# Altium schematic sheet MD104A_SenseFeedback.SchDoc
size Letter; Date: Not shown in title block; ApprovedBy: Not shown in title block; CheckedBy: Not shown in title block; Author: Not shown in title block; CompanyName: Not shown in title block; Engineer: Not shown in title block; Organization: Not shown in title block; Address1: Not shown in title block; Address2: Not shown in title block; Address3: Not shown in title block; Address4: Not shown in title block; DocumentNumber: 3; Revision: Use project parameter SCH_Rev; SheetNumber: 3; SheetTotal: 5; PageSetup: Record=PageOptions¦CenterHorizontal=True¦CenterVertical=True¦PrintScale=1.00¦XCorrection=1.00¦YCorrection=1.00¦PrintKind=0¦BorderSize=5000000¦LeftOffset=0¦BottomOffset=0¦Orientation=2¦PaperLength=1000¦PaperWidth=1000¦Scale=100¦PaperSource=15¦PrintQuality=600¦MediaType=1¦DitherType=10¦PaperKind=Letter¦PrintScaleMode=1
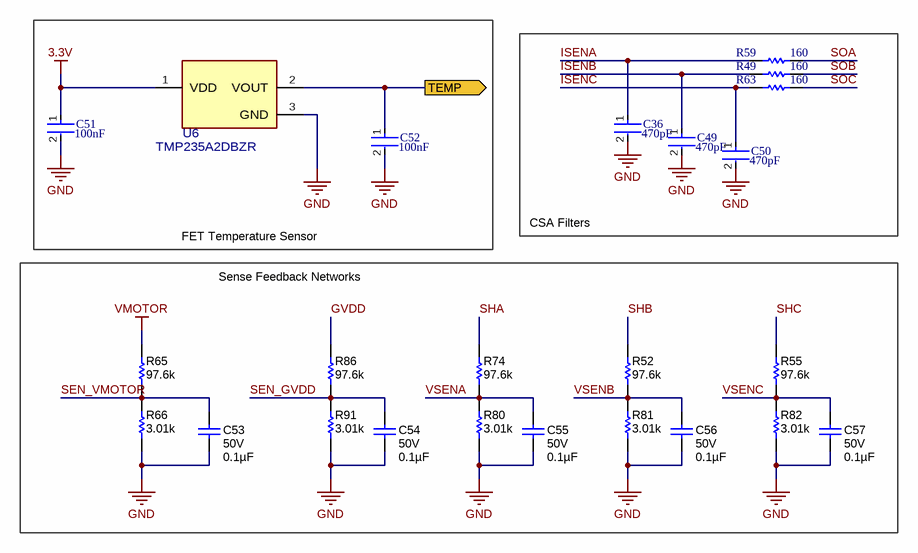
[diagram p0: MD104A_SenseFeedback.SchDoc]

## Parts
C36  Capacitance: 470pF  [FP-CL10-IPC_A]  (hidden comment: CL10C471JB81PNL)
C49  Capacitance: 470pF  [FP-CL10-IPC_A]  (hidden comment: CL10C471JB81PNL)
C50  Capacitance: 470pF  [FP-CL10-IPC_A]  (hidden comment: CL10C471JB81PNL)
C51  Capacitance: 100nF  [FP-GCM155-0_05-IPC_A]  (hidden comment: GCM155R71C104KA55J)
C52  Capacitance: 100nF  [FP-GCM155-0_05-IPC_A]  (hidden comment: GCM155R71C104KA55J)
C53  Value2: 50V  ValueDisplayed: 0.1µF  [0603L]  (hidden comment: C0603C104K5RACAUTO)
C54  Value2: 50V  ValueDisplayed: 0.1µF  [0603L]  (hidden comment: C0603C104K5RACAUTO)
C55  Value2: 50V  ValueDisplayed: 0.1µF  [0603L]  (hidden comment: C0603C104K5RACAUTO)
C56  Value2: 50V  ValueDisplayed: 0.1µF  [0603L]  (hidden comment: C0603C104K5RACAUTO)
C57  Value2: 50V  ValueDisplayed: 0.1µF  [0603L]  (hidden comment: C0603C104K5RACAUTO)
R49  160  [RESC1608X55X30ML15T15]
R52  ValueDisplayed: 97.6k  [0603L]  (hidden comment: CRCW060397K6FKEA)
R55  ValueDisplayed: 97.6k  [0603L]  (hidden comment: CRCW060397K6FKEA)
R59  160  [RESC1608X55X30ML15T15]
R63  160  [RESC1608X55X30ML15T15]
R65  ValueDisplayed: 97.6k  [0603L]  (hidden comment: CRCW060397K6FKEA)
R66  ValueDisplayed: 3.01k  [0603L]  (hidden comment: CRCW06033K01FKEA)
R74  ValueDisplayed: 97.6k  [0603L]  (hidden comment: CRCW060397K6FKEA)
R80  ValueDisplayed: 3.01k  [0603L]  (hidden comment: CRCW06033K01FKEA)
R81  ValueDisplayed: 3.01k  [0603L]  (hidden comment: CRCW06033K01FKEA)
R82  ValueDisplayed: 3.01k  [0603L]  (hidden comment: CRCW06033K01FKEA)
R86  ValueDisplayed: 97.6k  [0603L]  (hidden comment: CRCW060397K6FKEA)
R91  ValueDisplayed: 3.01k  [0603L]  (hidden comment: CRCW06033K01FKEA)
U6  TMP235A2DBZR  [DBZ0003A-MFG]

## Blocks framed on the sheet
FET Temperature Sensor: C51 C52 U6
CSA Filters: C36 C49 C50 R49 R59 R63
Sense Feedback Networks: C53-C57 R52 R55 R65 R66 R74 R80-R82 R86 R91

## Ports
TEMP (out)

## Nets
3.3V: C51.1 U6.1(VDD)
GND: C36.2 C49.2 C50.2 C51.2 C52.2 C53.1 C54.1 C55.1 C56.1 C57.1 R66.1 R80.1 R81.1 R82.1 R91.1 U6.3(GND)
VMOTOR: R65.2
GVDD: R86.2
ISENA: C36.1 R59.1
ISENB: C49.1 R49.1
ISENC: C50.1 R63.1
SEN_GVDD: C54.2 R86.1 R91.2
SEN_VMOTOR: C53.2 R65.1 R66.2
SHA: R74.2
SHB: R52.2
SHC: R55.2
SOA: R59.2
SOB: R49.2
SOC: R63.2
TEMP: C52.1 U6.2(VOUT) ; port TEMP
VSENA: C55.2 R74.1 R80.2
VSENB: C56.2 R52.1 R81.2
VSENC: C57.2 R55.1 R82.2

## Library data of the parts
C36 C49 C50 = CMP-13271-000890-1: Cap Ceramic 470pF 50V C0G ±5% Pad SMD 0603 +125°C T/R CL10C471JB81PNL
C51 C52 = CMP-2008-03712-2: Ceramic Capacitor for Automotive 100nF ±10% 16VDC X7R 0402 Paper T/R GCM155R71C104KA55J; Voltage Rating: 16V
C53-C57 = CMP-0079602-1: CAP, CERM, 0.1 µF, 50 V,+/- 10%, X7R, AEC-Q200 Grade 1, 0603; Manufacturer: Kemet; TaMin_C: -55°C; Polarized: N; SizeAreaWB_mm2: 4.68; U/M: EA; Value: 0.1uF; TaMax_C: 125°C; SizeZ_mm: 1; SizeX_mm: 1.6; SizeY_mm: 0.8; Cap_Case: 0603; SizeArea_mm2: 1.28; AEC Qualified: Y; Cap_F: 100nF; AEC Category: Q200
R49 R59 R63 = CMP-2000-00728-1: 160, 0.1W, 0603, AEC-Q200 ERJ-3GEYJ161V; Manufacturer: Panasonic
R52 R55 R65 R74 R86 = CMP-0022663-4: RES, 97.6 k, 1%, 0.1 W, AEC-Q200 Grade 0, 0603; Manufacturer: Vishay-Dale; Power_W: 100mW; TempCo: 100 ppm/C; Value_Code: 97k6; Value: 97.6k; EIA_Code: E96; SizeX_mm: 1.6; SizeY_mm: 0.8; SizeZ_mm: 1; Value2: 0.1W; SizeArea_mm2: 1.28; AEC Qualified: Y; VDC_V: 75V; AEC Category: Q200; AEC Grade: 0
R66 R80-R82 R91 = CMP-0022371-4: RES, 3.01 k, 1%, 0.1 W, AEC-Q200 Grade 0, 0603; Manufacturer: Vishay-Dale; Power_W: 100mW; TempCo: 100 ppm/C; Value_Code: 3k01; Value: 3.01k; EIA_Code: E96; SizeX_mm: 1.6; SizeY_mm: 0.8; SizeZ_mm: 1; Value2: 0.1W; SizeArea_mm2: 1.28; AEC Qualified: Y; VDC_V: 75V; AEC Category: Q200; AEC Grade: 0
U6 = CMP-0088337-2: Temperature Sensor Analog, Local -40°C ~ 150°C 10mV/°C SOT-23-3; Manufacturer: Texas Instruments; Accuracy: 0.5%; AEC Qualified: No; Operating Supply Current: 9uA; Sensor Output: Analog Voltage; TJmax_C: +150°C; SizeZ_mm: 1.12mm; Max Supply Voltage: 5.5V; Standoff Height: 0.01mm; Min Supply Voltage: 2.3V; AEC Category: Q200; CompType: IC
